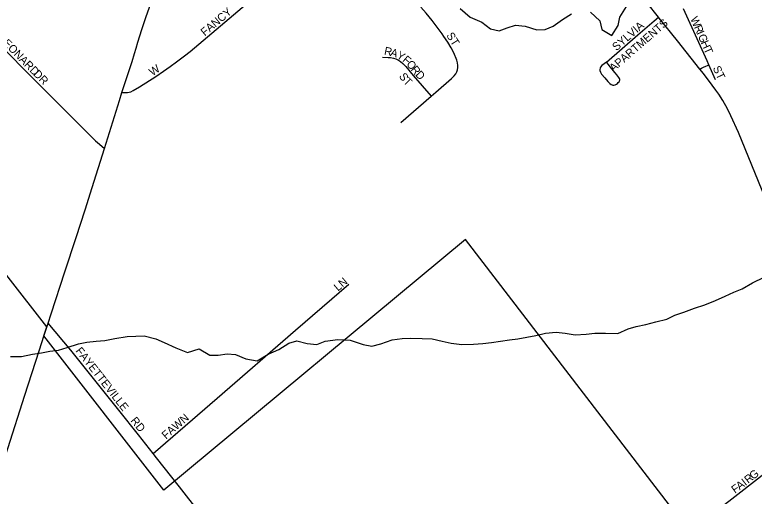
# Model space of a CAD drawing. Extents: x 1442749 to 1756758, y 235267 to 677782.
# Drawn here: x 1545014 to 1549629, y 469260 to 472266 of the extents above; entities that cross this region are included whole.
import ezdxf

# ---------------------------------------------------------------- set-up
doc = ezdxf.new("R2010")
doc.units = 0
for name, color, linetype in [('GM_X_City_Street', 7, 'Continuous'), ('GM_X_City_Street_Text', 7, 'Continuous'), ('GM_X_Corporation', 7, 'Continuous'), ('GM_X_County_Road', 7, 'Continuous'), ('GM_X_Minor_River', 7, 'Continuous'), ('GM_X_State_Route', 7, 'Continuous')]:
    doc.layers.add(name, color=color, linetype=linetype)

msp = doc.modelspace()

# ---------------------------------------------------------------- linework, layer by layer
at = {"layer": 'GM_X_City_Street'}
for points in [[(1545682.5, 471781.3), (1545701.9, 471781.3), (1545718.1, 471781.3), (1545727.6, 471782), (1545737.5, 471784.9), (1545752.4, 471792.3), (1545791.7, 471816.4), (1545894.6, 471881.2), (1545942.5, 471913.5), (1545984.4, 471941.9), (1546024, 471971.3), (1546072.6, 472008.5), (1546108.2, 472037.1), (1546432.6, 472311.4), (1546773, 472599.4), (1546868, 472680.1), (1547095.6, 472875.2)], [(1547611.7, 471756.7), (1547641, 471782), (1547740.2, 471867.9), (1547756.5, 471884.6), (1547766.6, 471898), (1547773, 471909.9), (1547777.5, 471922.7), (1547779.8, 471936), (1547780, 471949.5), (1547777.5, 471966.1), (1547772.7, 471982.2), (1547753.3, 472027.7), (1547736.8, 472059.9), (1547716.5, 472093.9), (1547692.6, 472129.6), (1547681.2, 472145.7), (1547661.9, 472172.2), (1547618.3, 472229.5), (1547581.3, 472275.5), (1547547.9, 472313.3)], [(1549345.5, 471952.5), (1549334.6, 471978.2), (1549283, 472092.1), (1549188, 472301.8)], [(1548706.5, 471969.6), (1548903.6, 472140.9), (1549005.3, 472228.7), (1549030.7, 472250.6)], [(1544898.6, 472102.4), (1544956.3, 472041.7), (1545097.4, 471899.5), (1545352.4, 471644.1), (1545481.8, 471513.2), (1545517.2, 471478.7), (1545542.3, 471457), (1545573.1, 471430.4)], [(1547308.6, 472001.9), (1547345.1, 471999.4), (1547358.1, 471998), (1547377.4, 471994.7), (1547393.1, 471990), (1547407.8, 471983), (1547421.2, 471973.9), (1547436, 471961), (1547454, 471942.1), (1547500.4, 471887.1), (1547611.7, 471756.7)], [(1548706.5, 471969.6), (1548677, 471948), (1548669.9, 471939.4), (1548666.7, 471932.5), (1548665.4, 471924.9), (1548665.9, 471917.3), (1548669.4, 471906.7), (1548675.6, 471895.8), (1548696.1, 471871.1), (1548715.9, 471848.6), (1548727.7, 471836.8), (1548736.6, 471830.6), (1548741.9, 471828.2), (1548747.1, 471827.1), (1548752.9, 471827.1), (1548760.8, 471828.2), (1548768.7, 471832.1), (1548775.5, 471836.9), (1548780.8, 471842.4), (1548785.6, 471847.1), (1548789.2, 471852.9), (1548790.3, 471858.2), (1548789.9, 471863.4), (1548788.8, 471867.4), (1548784.9, 471874.1), (1548772.2, 471889.9), (1548730.3, 471941.5), (1548718.8, 471955.5), (1548706.5, 471969.6)], [(1549290.5, 471926.6), (1549299.2, 471931.4), (1549312.3, 471938.5), (1549326.1, 471945.1), (1549337.1, 471949.2), (1549345.5, 471952.5)], [(1549386.8, 471860.4), (1549345.5, 471952.5)], [(1547422.5, 471593.9), (1547611.7, 471756.7)], [(1545877.6, 469526.9), (1546276.1, 469872.8), (1546764.9, 470296.2), (1547097.8, 470583.6)], [(1545877.6, 469526.9), (1545785.2, 469644.2), (1545662.3, 469798), (1545363.7, 470172.5), (1545222.4, 470340.8)], [(1549387, 469165.7), (1549545.3, 469288.5), (1549698.5, 469406.6), (1549890.2, 469555.4), (1550244.7, 469832.7)], [(1546042.1, 469318.9), (1545898.9, 469499.9), (1545877.6, 469526.9)]]:
    msp.add_lwpolyline(points, dxfattribs=at)
at = {"layer": 'GM_X_Corporation'}
msp.add_lwpolyline([(1550125.8, 467867.6), (1547827.6, 470863.4), (1545943.2, 469298.6), (1545194.2, 470260.5), (1545212.9, 470317.8), (1543492.6, 472527)], dxfattribs=at)
at = {"layer": 'GM_X_County_Road'}
msp.add_lwpolyline([(1547392, 467606.4), (1547174.3, 467882), (1546913.4, 468215.1), (1546759.3, 468411.1), (1546688.1, 468501.2), (1546431.7, 468825.4), (1546099.9, 469244.8), (1546042.1, 469318.9)], dxfattribs=at)
at = {"layer": 'GM_X_Minor_River'}
for points in [[(1547792.9, 472305.3), (1547856.1, 472250.4), (1547929.7, 472219.3), (1547983.2, 472178.5), (1548037.1, 472165.7), (1548087.4, 472185.1), (1548139.7, 472200.4), (1548199.6, 472193.6), (1548271.4, 472172.5), (1548323.5, 472173.8), (1548373.8, 472195.2), (1548432.5, 472236.5), (1548489.1, 472271.8)], [(1548607.3, 472282.2), (1548664.6, 472227.3), (1548677.8, 472173), (1548741.4, 472136.1), (1548780.3, 472197.7), (1548791.1, 472249.7), (1548832.1, 472317.3)], [(1544986.5, 470132.5), (1545056.5, 470131.5), (1545124.8, 470146.6), (1545181, 470155.9), (1545233.2, 470165.2), (1545287.4, 470172.5), (1545341.6, 470187.8), (1545412, 470210.9), (1545464.3, 470222.2), (1545522.4, 470227.4), (1545576.5, 470232.7), (1545638.8, 470243.9), (1545715, 470256.9), (1545769.1, 470260.1), (1545821.2, 470261.4), (1545895, 470242.4), (1545946.7, 470219.6), (1546018.3, 470186.6), (1546092, 470157.5), (1546164.4, 470180.6), (1546231.9, 470141.6), (1546283.9, 470140.9), (1546340.1, 470148.1), (1546392.1, 470145.4), (1546455.8, 470118.5), (1546525.6, 470105.5), (1546594.3, 470146.7), (1546662.8, 470175.8), (1546723.4, 470215.1), (1546773.7, 470230.4), (1546839.5, 470213.5), (1546899.5, 470206.6), (1546951.8, 470228), (1547030.1, 470239), (1547108.1, 470233.9), (1547187.8, 470206.7), (1547241.7, 470196), (1547298, 470211.2), (1547368.4, 470236.3), (1547432.6, 470245.5), (1547482.7, 470246.8), (1547556.7, 470243.8), (1547618.7, 470243), (1547680.6, 470228.1), (1547738.5, 470215.3), (1547804.4, 470206.3), (1547876.5, 470209.4), (1547934.6, 470212.6), (1547988.8, 470219.9), (1548045, 470229.1), (1548101.1, 470236.4), (1548153.3, 470243.7), (1548209.5, 470253), (1548265.7, 470264.2), (1548326, 470277.4), (1548392.1, 470284.5), (1548448.1, 470277.8), (1548512, 470266.9), (1548580.1, 470272), (1548634.3, 470277.2), (1548700.4, 470278.3), (1548778.4, 470275.3), (1548842.9, 470304.5), (1548893.1, 470319.8), (1548953.4, 470333), (1549015.7, 470348.2), (1549084, 470365.3), (1549134.4, 470390.7), (1549188.8, 470410), (1549257.2, 470433.1), (1549321.5, 470454.3), (1549388, 470481.5), (1549448.4, 470508.7), (1549502.9, 470534), (1549553.2, 470555.4), (1549617.8, 470592.6), (1549690.4, 470627.7)]]:
    msp.add_lwpolyline(points, dxfattribs=at)
at = {"layer": 'GM_X_State_Route'}
for points in [[(1549698.2, 471122.6), (1549530.3, 471530.4), (1549483.5, 471635.2), (1549461.4, 471679.4), (1549432.6, 471731.3), (1549407.4, 471769.8), (1549389.9, 471794.8), (1549367.7, 471826.4), (1549312, 471899.4), (1549290.5, 471926.6), (1549151.2, 472102.6), (1549035.2, 472244.9), (1549030.7, 472250.6), (1548958.1, 472342.4), (1548897.6, 472420), (1548669, 472707.5), (1548590.2, 472801)], [(1545666.9, 471731.2), (1545682.5, 471781.3), (1545745.4, 471973.1), (1545760.1, 472023.2), (1545770.9, 472057.5), (1545782, 472095.1), (1545806.1, 472173.3), (1545830.9, 472247.8), (1545854, 472312.5), (1545875.6, 472363.6), (1545899.8, 472413.5), (1545919.4, 472450), (1545936.5, 472479), (1545958.7, 472515.3), (1545978.9, 472545.3), (1546004.5, 472581.1), (1546021.2, 472601.6), (1546037.1, 472620.1), (1546057.6, 472643.1), (1546086, 472671.7), (1546134, 472716), (1546173.4, 472750.2)], [(1545222.4, 470340.8), (1545240.9, 470398.7), (1545325.3, 470661), (1545396.6, 470876), (1545452.1, 471047.7), (1545497.5, 471188.2), (1545573.1, 471430.4), (1545666.9, 471731.2)], [(1545197.4, 470265.6), (1545222.4, 470340.8)], [(1544820.9, 469096.5), (1544970.3, 469558.6), (1545075.8, 469890), (1545165, 470168), (1545197.4, 470265.6)]]:
    msp.add_lwpolyline(points, dxfattribs=at)

# ---------------------------------------------------------------- texts
at = {"layer": 'GM_X_City_Street_Text'}
for s, rotation, p in [('FANCY', 40.0607, (1546199.6, 472130.1)), ('W', 293.8874, (1549228.3, 472241)), ('APARTMENTS', 41.0703, (1548750.8, 471906.7)), ('SYLVIA', 40.9692, (1548769.1, 472037.6)), ('R', 293.8848, (1549251.4, 472188.8)), ('I', 293.9013, (1549267.5, 472152.5)), ('LEONARD', 314.3843, (1544910, 472111.9)), ('ST', 302.7376, (1547705.2, 472136.8)), ('G', 293.8759, (1549276.4, 472132.4)), ('H', 293.8862, (1549294.2, 472092.2)), ('T', 293.8765, (1549312, 472052)), ('R', 348.4591, (1547316.2, 472017.7)), ('A', 342.7816, (1547353.8, 472010.1)), ('Y', 330.2904, (1547393.1, 471998.2)), ('F', 319.2831, (1547429.3, 471977.9)), ('O', 309.5285, (1547454.4, 471956.5)), ('W', 34.5154, (1545873, 471881.4)), ('R', 308.9784, (1547482.3, 471922.7)), ('ST', 295.0177, (1549369, 471933.2)), ('DR', 315, (1545125.5, 471891.9)), ('S', 304.2243, (1547409.2, 471882.3)), ('D', 314.1711, (1547510.5, 471888.2)), ('T', 314.701, (1547435.3, 471845.5)), ('LN', 40.5949, (1547031.1, 470537.2)), ('FAYETTEVILLE', 308.221, (1545390.2, 470166.3)), ('FAWN', 41.0551, (1545957.5, 469613.2)), ('RD', 308.6634, (1545733.4, 469730.7)), ('R', 37.7034, (1549591.3, 469336.8)), ('G', 37.7005, (1549622.6, 469361)), ('A', 37.2986, (1549538.6, 469296.4)), ('I', 37.6442, (1549573.8, 469323.3)), ('F', 35.949, (1549509, 469275))]:
    msp.add_text(s, height=50, rotation=rotation, dxfattribs=at).set_placement(p)

doc.saveas('drawing.dxf')
